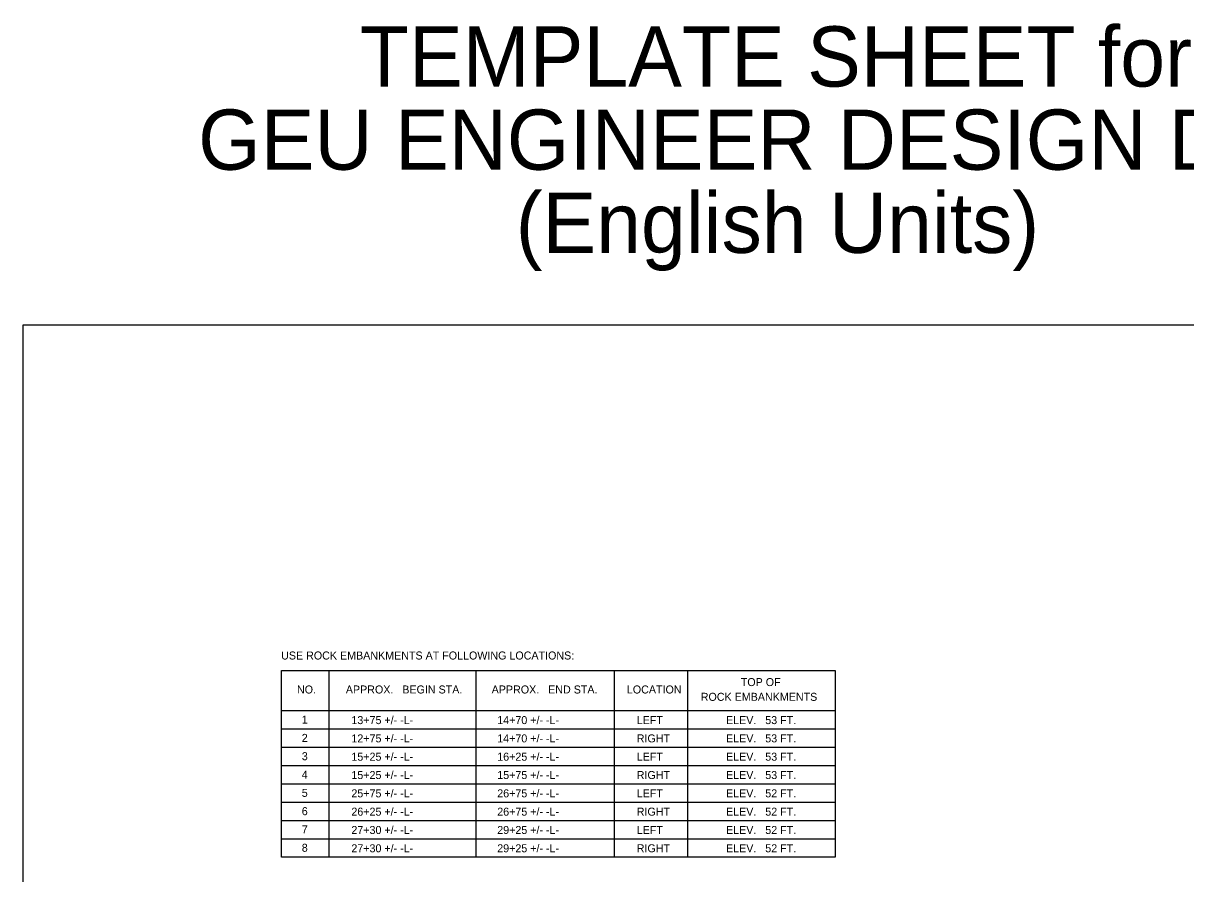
# Model space of a CAD drawing. Extents: x 2189223 to 2190097, y 563994 to 564498.
# Drawn here: x 2189347.8 to 2189702.6, y 564238.4 to 564497.9 of the extents above; entities that cross this region are included whole.
import ezdxf

# ---------------------------------------------------------------- set-up
doc = ezdxf.new("R2010")
doc.units = 0
doc.layers.add('Default', color=7, linetype='Continuous')
doc.layers.add('Geotech Sheets and Borders Cell', color=7, linetype='Continuous')

msp = doc.modelspace()

# ---------------------------------------------------------------- linework, layer by layer
at = {"layer": 'Default'}
for p, q in [((2189441.03, 564300.39), (2189441.03, 564243.43)), ((2189485.86, 564300.39), (2189485.86, 564243.43)), ((2189528.07, 564300.39), (2189528.07, 564243.43)), ((2189550.49, 564300.39), (2189550.49, 564243.43)), ((2189426.58, 564288.18), (2189595.59, 564288.18)), ((2189426.58, 564282.59), (2189595.59, 564282.59)), ((2189426.58, 564277), (2189595.59, 564277)), ((2189426.58, 564271.41), (2189595.59, 564271.41)), ((2189426.58, 564265.82), (2189595.59, 564265.82)), ((2189426.58, 564260.23), (2189595.59, 564260.23)), ((2189426.58, 564254.64), (2189595.59, 564254.64)), ((2189426.58, 564249.05), (2189595.59, 564249.05))]:
    msp.add_line(p, q, dxfattribs=at)
for points in [[(2189347.77, 564405.93), (2189877.15, 564405.93), (2189877.15, 564038.89), (2189347.77, 564038.89)], [(2189426.58, 564300.39), (2189595.59, 564300.39), (2189595.59, 564243.43), (2189426.58, 564243.43)]]:
    msp.add_lwpolyline(points, close=True, dxfattribs=at)

# ---------------------------------------------------------------- texts
for s, height, p in [('USE ROCK EMBANKMENTS AT FOLLOWING LOCATIONS:', 2.4419, (2189426.48, 564303.77)), ('TOP OF', 2.442, (2189566.76, 564295.66)), ('NO.', 2.442, (2189431.32, 564293.4)), ('APPROX.   BEGIN STA.', 2.4419, (2189446.22, 564293.4)), ('APPROX.   END STA.', 2.4419, (2189490.73, 564293.4)), ('LOCATION', 2.442, (2189532, 564293.4)), ('ROCK EMBANKMENTS', 2.4419, (2189554.55, 564291.16)), ('1', 2.44, (2189432.78, 564284.22)), ('13+75 +/- -L-', 2.4419, (2189447.92, 564284.06)), ('14+70 +/- -L-', 2.4419, (2189492.43, 564284.06)), ('LEFT', 2.442, (2189535.01, 564284.06)), ('ELEV.   53 FT.', 2.4419, (2189562.26, 564284.06)), ('2', 2.44, (2189432.78, 564278.63)), ('12+75 +/- -L-', 2.4419, (2189447.92, 564278.48)), ('14+70 +/- -L-', 2.4419, (2189492.43, 564278.48)), ('RIGHT', 2.442, (2189535.01, 564278.48)), ('ELEV.   53 FT.', 2.4419, (2189562.26, 564278.48)), ('3', 2.44, (2189432.78, 564273.04)), ('15+25 +/- -L-', 2.4419, (2189447.92, 564272.89)), ('16+25 +/- -L-', 2.4419, (2189492.43, 564272.89)), ('LEFT', 2.442, (2189535.01, 564272.89)), ('ELEV.   53 FT.', 2.4419, (2189562.26, 564272.89)), ('4', 2.44, (2189432.78, 564267.45)), ('15+25 +/- -L-', 2.4419, (2189447.92, 564267.3)), ('15+75 +/- -L-', 2.4419, (2189492.43, 564267.3)), ('RIGHT', 2.442, (2189535.01, 564267.3)), ('ELEV.   53 FT.', 2.4419, (2189562.26, 564267.3)), ('5', 2.44, (2189432.78, 564261.86)), ('25+75 +/- -L-', 2.4419, (2189447.92, 564261.71)), ('26+75 +/- -L-', 2.4419, (2189492.43, 564261.71)), ('LEFT', 2.442, (2189535.01, 564261.71)), ('ELEV.   52 FT.', 2.4419, (2189562.26, 564261.71)), ('6', 2.44, (2189432.78, 564256.27)), ('26+25 +/- -L-', 2.4419, (2189447.92, 564256.12)), ('26+75 +/- -L-', 2.4419, (2189492.43, 564256.12)), ('RIGHT', 2.442, (2189535.01, 564256.12)), ('ELEV.   52 FT.', 2.4419, (2189562.26, 564256.12)), ('7', 2.44, (2189432.78, 564250.68)), ('27+30 +/- -L-', 2.4419, (2189447.92, 564250.53)), ('29+25 +/- -L-', 2.4419, (2189492.43, 564250.53)), ('LEFT', 2.442, (2189535.01, 564250.53)), ('ELEV.   52 FT.', 2.4419, (2189562.26, 564250.53)), ('8', 2.44, (2189432.78, 564245.1)), ('27+30 +/- -L-', 2.4419, (2189447.92, 564244.94)), ('29+25 +/- -L-', 2.4419, (2189492.43, 564244.94)), ('RIGHT', 2.442, (2189535.01, 564244.94)), ('ELEV.   52 FT.', 2.4419, (2189562.26, 564244.94))]:
    msp.add_text(s, height=height, dxfattribs=at).set_placement(p)
at = {"layer": 'Geotech Sheets and Borders Cell'}
for s, p in [('TEMPLATE SHEET for', (2189450.48, 564478.6)), ('GEU ENGINEER DESIGN DETAIL', (2189401.14, 564453.22)), ('(English Units)', (2189498.08, 564427.85))]:
    msp.add_text(s, height=18.3751, dxfattribs=at).set_placement(p)

doc.saveas('drawing.dxf')
